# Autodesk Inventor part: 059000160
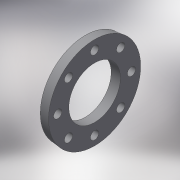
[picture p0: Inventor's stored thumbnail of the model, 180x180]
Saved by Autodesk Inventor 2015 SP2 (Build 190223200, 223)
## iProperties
Created: 2017-10
Part Number: 059000160
Material: Generic
Description: PLASSON BACKING FLANGE PVC 160
Document SubType Name: Modeling
Designer: KIM
Density: 1 g/cm^3
Appearance: Default
Author: KIM
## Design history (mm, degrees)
derived "059000.ipt"
feature "Solid1::059000.ipt"
tag "TaggingFeature1"
body "Solid1"
other parameters: "d1" = 193, "d2" = 289, "d3" = 283.22, "d5" = 22, "d6" = 120.5, "d8" = 0, "d10" = 360 deg, "E_" = 193, "E_1" = 289, "Dp_" = 241, "S_" = 22
